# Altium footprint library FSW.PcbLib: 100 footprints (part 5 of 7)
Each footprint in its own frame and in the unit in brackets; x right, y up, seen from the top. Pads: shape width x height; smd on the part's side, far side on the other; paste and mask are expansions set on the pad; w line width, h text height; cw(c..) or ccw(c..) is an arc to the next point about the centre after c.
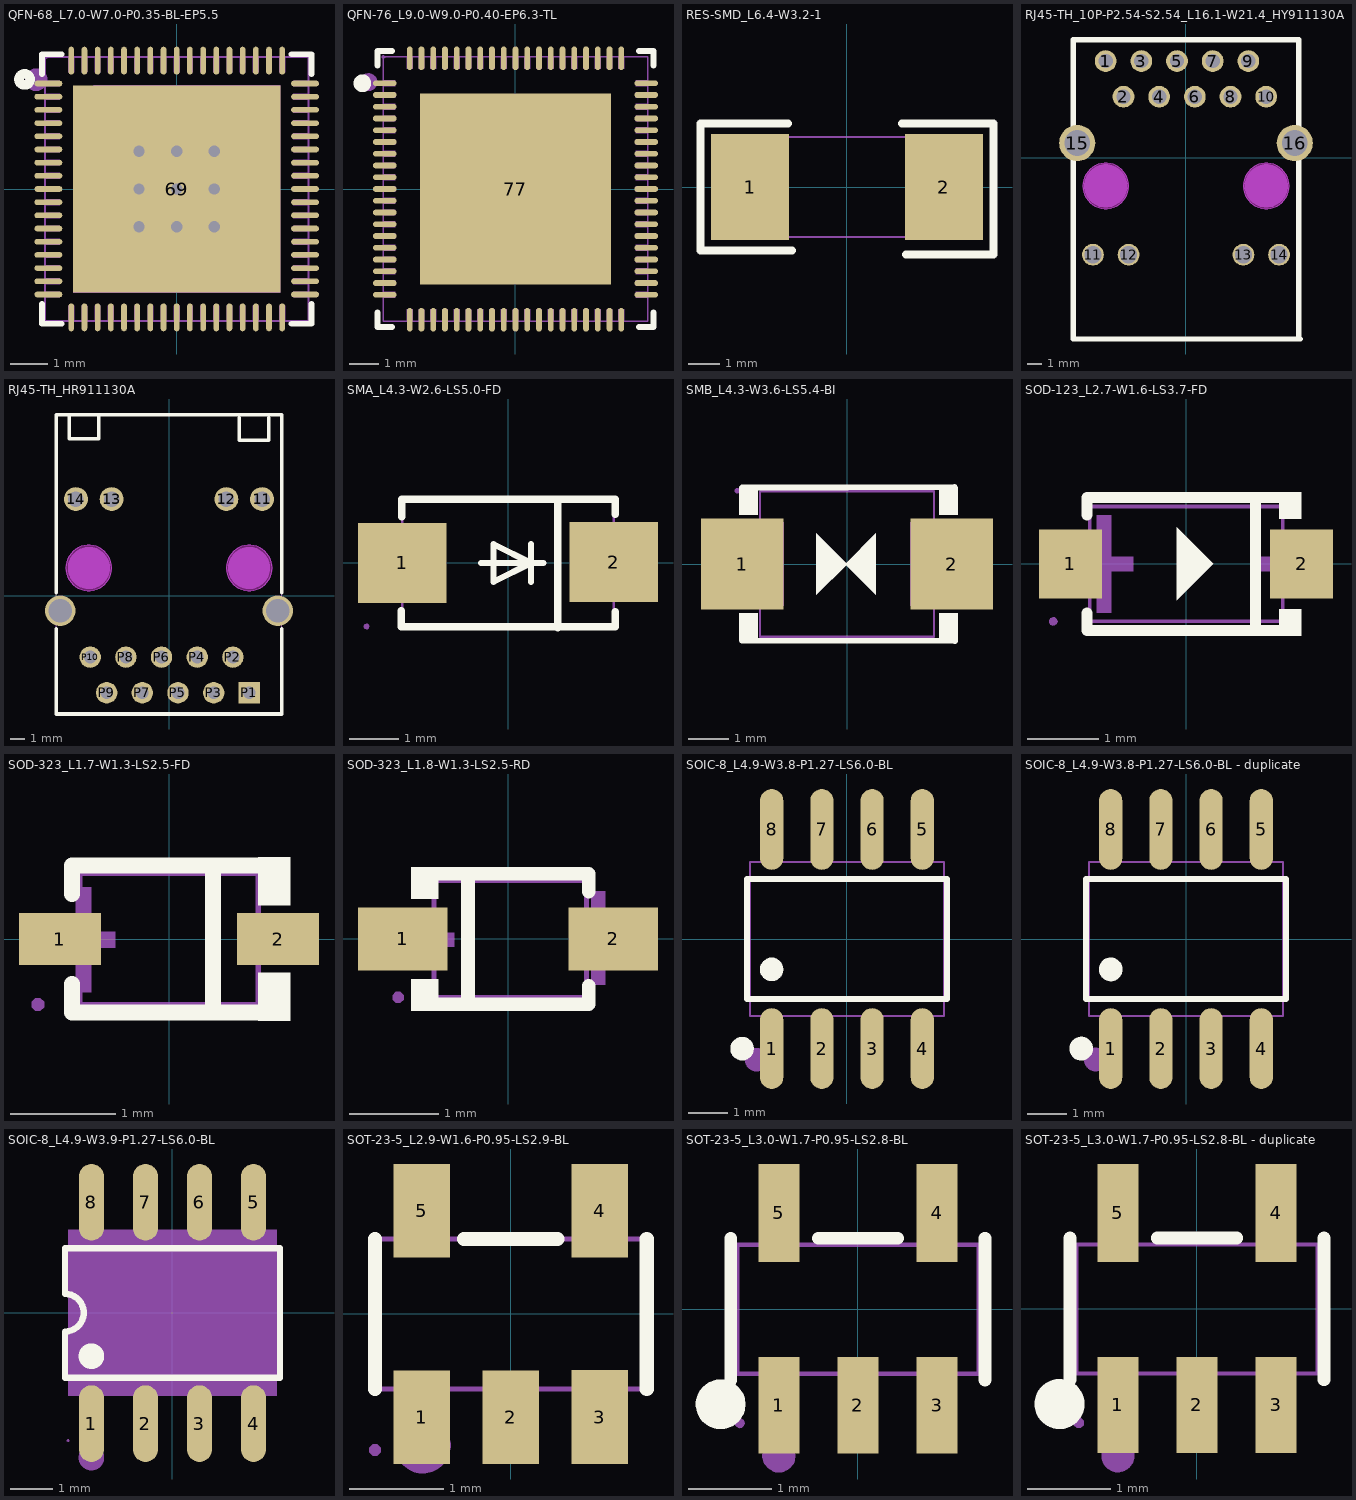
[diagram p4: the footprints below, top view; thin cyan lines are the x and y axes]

## QFN-68_L7.0-W7.0-P0.35-BL-EP5.5 [mm]
pads (69):
  oval 0.74x0.15 smd paste-100 mask+0.051: 1(-3.407,2.8) 2(-3.407,2.45) 3(-3.407,2.1) 4(-3.407,1.75) 5(-3.407,1.4) 6(-3.407,1.05) 7(-3.407,0.7) 8(-3.407,0.35) 9(-3.407,0) 10(-3.407,-0.35) 11(-3.407,-0.7) 12(-3.407,-1.05) 13(-3.407,-1.4) 14(-3.407,-1.75) 15(-3.407,-2.1) 16(-3.407,-2.45) 17(-3.407,-2.8) 35(3.407,-2.8) 36(3.407,-2.45) 37(3.407,-2.1) 38(3.407,-1.75) 39(3.407,-1.4) 40(3.407,-1.05) 41(3.407,-0.7) 42(3.407,-0.35) 43(3.407,0) 44(3.407,0.35) 45(3.407,0.7) 46(3.407,1.05) 47(3.407,1.4) 48(3.407,1.75) 49(3.407,2.1) 50(3.407,2.45) 51(3.407,2.8)
  oval 0.15x0.74 smd paste-100 mask+0.051: 18(-2.8,-3.407) 19(-2.45,-3.407) 20(-2.1,-3.407) 21(-1.75,-3.407) 22(-1.4,-3.407) 23(-1.05,-3.407) 24(-0.7,-3.407) 25(-0.35,-3.407) 26(0,-3.407) 27(0.35,-3.407) 28(0.7,-3.407) 29(1.05,-3.407) 30(1.4,-3.407) 31(1.75,-3.407) 32(2.1,-3.407) 33(2.45,-3.407) 34(2.8,-3.407) 52(2.8,3.407) 53(2.45,3.407) 54(2.1,3.407) 55(1.75,3.407) 56(1.4,3.407) 57(1.05,3.407) 58(0.7,3.407) 59(0.35,3.407) 60(0,3.407) 61(-0.35,3.407) 62(-0.7,3.407) 63(-1.05,3.407) 64(-1.4,3.407) 65(-1.75,3.407) 66(-2.1,3.407) 67(-2.45,3.407) 68(-2.8,3.407)
  rect 5.5x5.5 smd paste-100 mask+0.051: 69(0,0)
via 1,-1 diameter 0.6 hole 0.3
via 0,-1 diameter 0.6 hole 0.3
via -1,-1 diameter 0.6 hole 0.3
via 1,0 diameter 0.6 hole 0.3
via 0,0 diameter 0.6 hole 0.3
via -1,0 diameter 0.6 hole 0.3
via 1,1 diameter 0.6 hole 0.3
via 0,1 diameter 0.6 hole 0.3
via -1,1 diameter 0.6 hole 0.3
Top Overlay:
  circle w0.254: c-4.04,2.91 r0.148
  lines w0.152: -3.576,-3.05 -3.576,-3.576 -3.05,-3.576 ; -3.576,3.05 -3.576,3.576 -3.05,3.576 ; 3.05,-3.576 3.576,-3.576 3.576,-3.05 ; 3.05,3.576 3.576,3.576 3.576,3.05
Top Paste:
  drawing of 69 lines, arcs and shapes, not listed
Mechanical 2:
  circle w0.3: c-3.73,2.9 r0.15
Mechanical 6:
  lines w0.051: -3.5,-3.5 -3.5,3.5 3.5,3.5 3.5,-3.5 -3.5,-3.5
Mechanical 8:
  region: -3.44,3.5 -3.44,3.475 -3.475,3.44 -3.525,3.44 -3.56,3.475 -3.56,3.5 -3.56,3.525 -3.525,3.56 -3.475,3.56 -3.44,3.525 -3.44,3.5
Mechanical 9:
  drawing of 69 lines, arcs and shapes, not listed
3D body "QFN-68_L7.0-W7.0-P0.35-BL-EP5.5.step": height 0.75, standoff 0, extent -3.5,-3.5 3.5,3.5

## QFN-76_L9.0-W9.0-P0.40-EP6.3-TL [mm]
pads (77):
  oval 0.8x0.2 smd paste-100 mask+0.051: 1(-4.45,3.599) 2(-4.45,3.2) 3(-4.45,2.799) 4(-4.45,2.4) 5(-4.45,1.999) 6(-4.45,1.6) 7(-4.45,1.199) 8(-4.45,0.8) 9(-4.45,0.399) 10(-4.45,0) 11(-4.45,-0.399) 12(-4.45,-0.8) 13(-4.45,-1.199) 14(-4.45,-1.6) 15(-4.45,-1.999) 16(-4.45,-2.4) 17(-4.45,-2.799) 18(-4.45,-3.2) 19(-4.45,-3.599) 39(4.45,-3.599) 40(4.45,-3.2) 41(4.45,-2.799) 42(4.45,-2.4) 43(4.45,-1.999) 44(4.45,-1.6) 45(4.45,-1.199) 46(4.45,-0.8) 47(4.45,-0.399) 48(4.45,0) 49(4.45,0.399) 50(4.45,0.8) 51(4.45,1.199) 52(4.45,1.6) 53(4.45,1.999) 54(4.45,2.4) 55(4.45,2.799) 56(4.45,3.2) 57(4.45,3.599)
  oval 0.2x0.8 smd paste-100 mask+0.051: 20(-3.599,-4.45) 21(-3.2,-4.45) 22(-2.799,-4.45) 23(-2.4,-4.45) 24(-1.999,-4.45) 25(-1.6,-4.45) 26(-1.199,-4.45) 27(-0.8,-4.45) 28(-0.399,-4.45) 29(0,-4.45) 30(0.399,-4.45) 31(0.8,-4.45) 32(1.199,-4.45) 33(1.6,-4.45) 34(1.999,-4.45) 35(2.4,-4.45) 36(2.799,-4.45) 37(3.2,-4.45) 38(3.599,-4.45) 58(3.599,4.45) 59(3.2,4.45) 60(2.799,4.45) 61(2.4,4.45) 62(1.999,4.45) 63(1.6,4.45) 64(1.199,4.45) 65(0.8,4.45) 66(0.399,4.45) 67(0,4.45) 68(-0.399,4.45) 69(-0.8,4.45) 70(-1.199,4.45) 71(-1.6,4.45) 72(-1.999,4.45) 73(-2.4,4.45) 74(-2.799,4.45) 75(-3.2,4.45) 76(-3.599,4.45)
  rect 6.5x6.5 smd paste-100 mask+0.051: 77(0,0)
Top Overlay:
  lines w0.2: -4.7,-4.2 -4.7,-4.7 -4.2,-4.7 ; -4.7,4.2 -4.7,4.7 -4.2,4.7 ; 4.2,-4.7 4.7,-4.7 4.7,-4.2 ; 4.2,4.7 4.7,4.7 4.7,4.2
  lines w0.3: -5.06,3.597 cw(c-5.21,3.599) -5.06,3.6
Top Paste:
  drawing of 77 lines, arcs and shapes, not listed
Mechanical 2:
  circle w0.3: c-5,3.64 r0.15
Mechanical 6:
  lines w0.051: -4.5,-4.5 -4.5,4.5 4.5,4.5 4.5,-4.5 -4.5,-4.5
Mechanical 8:
  region: -4.44,4.5 -4.44,4.475 -4.475,4.44 -4.525,4.44 -4.56,4.475 -4.56,4.5 -4.56,4.525 -4.525,4.56 -4.475,4.56 -4.44,4.525 -4.44,4.5
Mechanical 9:
  drawing of 77 lines, arcs and shapes, not listed
3D body "QFN-76_L9.0-W9.0-P0.40-EP6.3-TL.step": height 0.85, standoff 0, extent -4.5,-4.5 4.5,4.5

## RES-SMD_L6.4-W3.2-1 [mil]
pads (2):
  rect 98.4x133.9 smd: 1(-122,0) 2(122.1,0)
Top Overlay:
  lines w10: -74.5,80 -184.5,80 -184.5,-80 -69.5,-80 ; 69.6,80 184.6,80 184.6,-85 74.6,-85
Mechanical 6:
  lines w2: -126,-63 -126,63 126,63 126,-63 -126,-63
Mechanical 8:
  region: -123.6,-63 -124,-64.3 -125,-65.1 -126.3,-65.3 -127.5,-64.8 -128.2,-63.7 -128.2,-62.3 -127.5,-61.2 -126.3,-60.7 -125,-60.8 -124,-61.7
Mechanical 9:
  region: 90.6,63 126,63 126,-63 90.6,-63
  region: -126,63 -90.5,63 -90.5,-63 -126,-63

## RJ45-TH_10P-P2.54-S2.54_L16.1-W21.4_HY911130A [mil]
pads (16):
  round 61 hole 40: 1(-225.19,271.45) 2(-175.19,171.46) 3(-125.19,271.45) 4(-75.19,171.46) 5(-25.19,271.45) 6(24.81,171.46) 7(74.81,271.45) 8(124.81,171.46) 9(174.81,271.45) 10(224.81,171.46)
  round 61 hole 48: 11(-260.82,-271.46) 12(-160.82,-271.46) 13(160.83,-271.46) 14(260.83,-271.46)
  round 101.6 hole 72: 15(-304.92,41.53) 16(304.92,41.53)
Top Overlay:
  lines w15.24: 315.75,-507.68 315.75,330.9 -315.75,330.9 -315.75,-507.68 320.02,-507.68
Keep-Out Layer:
  board cut-out: 288.98,-78.55 288.98,-84.85 286.52,-97.21 281.69,-108.85 274.69,-119.33 265.78,-128.24 255.3,-135.24 243.66,-140.06 231.3,-142.52 218.7,-142.52 206.34,-140.06 194.7,-135.24 184.22,-128.24 175.31,-119.33 168.31,-108.85 163.48,-97.21 161.02,-84.85 161.02,-78.55 161.02,-72.24 163.48,-59.88 168.31,-48.24 175.31,-37.76 184.22,-28.85 194.7,-21.85 206.34,-17.03 218.7,-14.57 231.3,-14.57 243.66,-17.03 255.3,-21.85 265.78,-28.85 274.69,-37.76 281.69,-48.24 286.52,-59.88 288.98,-72.24 288.98,-78.55
  board cut-out: -161.02,-78.55 -161.02,-84.85 -163.48,-97.21 -168.31,-108.85 -175.31,-119.33 -184.22,-128.24 -194.7,-135.24 -206.34,-140.06 -218.7,-142.52 -231.3,-142.52 -243.66,-140.06 -255.3,-135.24 -265.78,-128.24 -274.69,-119.33 -281.69,-108.85 -286.52,-97.21 -288.98,-84.85 -288.98,-78.55 -288.98,-72.24 -286.52,-59.88 -281.69,-48.24 -274.69,-37.76 -265.78,-28.85 -255.3,-21.85 -243.66,-17.03 -231.3,-14.57 -218.7,-14.57 -206.34,-17.03 -194.7,-21.85 -184.22,-28.85 -175.31,-37.76 -168.31,-48.24 -163.48,-59.88 -161.02,-72.24 -161.02,-78.55
Keep-Out Layer:
  drawing of 6 lines, arcs and shapes, not listed
Mechanical 1:
  circle w0.1: c225,-78.55 r63.98
  circle w0.1: c-225,-78.55 r63.98
Mechanical 6:
  lines w2: -315.75,-507.68 -315.75,330.9 315.75,330.9 315.75,-507.68 -315.75,-507.68
Mechanical 8:
  region: -313.39,330.9 -313.39,329.93 -314.77,328.54 -316.73,328.54 -318.11,329.93 -318.11,330.9 -318.11,331.88 -316.73,333.26 -314.77,333.26 -313.39,331.88 -313.39,330.9
Mechanical 9:
  drawing of 18 lines, arcs and shapes, not listed

## RJ45-TH_HR911130A [mm]
pads (16):
  round 1.7 hole 1.1: 11(6.625,6.895) 12(4.085,6.895) 13(-4.085,6.895) 14(-6.625,6.895)
  rect 1.524x1.524 hole 0.91: P1(5.72,-6.895)
  round 1.524 hole 0.91: P2(4.549,-4.355) P3(3.18,-6.895) P4(2.009,-4.355) P5(0.64,-6.895) P6(-0.531,-4.355) P7(-1.9,-6.895) P8(-3.071,-4.355) P9(-4.44,-6.895) P10(-5.611,-4.355)
  round 2.159 hole 1.7: SHIELD0(-7.745,-1.055) SHIELD1(7.745,-1.055)
Top Overlay:
  lines w0.254: -8.02,-2.337 -8.02,-8.405 8.02,-8.405 8.02,-2.337 ; -8.02,0.226 -8.02,12.877 ; -8.02,12.895 8.02,12.895 8.02,0.226 ; -7.1,12.795 -7.1,11.195 -5,11.195 -5,11.995 -5,12.795 ; 4.999,12.695 4.999,11.095 7.099,11.095 7.099,11.895 7.099,12.695
Keep-Out Layer:
  board cut-out: 7.34,1.995 7.34,1.835 7.278,1.521 7.155,1.225 6.977,0.959 6.751,0.733 6.485,0.555 6.189,0.432 5.875,0.37 5.555,0.37 5.241,0.432 4.945,0.555 4.679,0.733 4.453,0.959 4.275,1.225 4.152,1.521 4.09,1.835 4.09,1.995 4.09,2.155 4.152,2.469 4.275,2.765 4.453,3.031 4.679,3.257 4.945,3.435 5.241,3.558 5.555,3.62 5.875,3.62 6.189,3.558 6.485,3.435 6.751,3.257 6.977,3.031 7.155,2.765 7.278,2.469 7.34,2.155 7.34,1.995
  board cut-out: -4.09,1.995 -4.09,1.835 -4.152,1.521 -4.275,1.225 -4.453,0.959 -4.679,0.733 -4.945,0.555 -5.241,0.432 -5.555,0.37 -5.875,0.37 -6.189,0.432 -6.485,0.555 -6.751,0.733 -6.977,0.959 -7.155,1.225 -7.278,1.521 -7.34,1.835 -7.34,1.995 -7.34,2.155 -7.278,2.469 -7.155,2.765 -6.977,3.031 -6.751,3.257 -6.485,3.435 -6.189,3.558 -5.875,3.62 -5.555,3.62 -5.241,3.558 -4.945,3.435 -4.679,3.257 -4.453,3.031 -4.275,2.765 -4.152,2.469 -4.09,2.155 -4.09,1.995
Keep-Out Layer:
  drawing of 6 lines, arcs and shapes, not listed
Mechanical 1:
  circle w0.003: c5.715,1.995 r1.625
  circle w0.003: c-5.715,1.995 r1.625
Mechanical 2:
  circle w1.5: c-5.7,1.995 r0.75
  circle w1.5: c5.7,1.995 r0.75
Mechanical 6:
  lines w0.051: -8.02,-8.405 8.02,-8.405 8.02,12.895 -8.02,12.895 -8.02,-8.405
Mechanical 8:
  region: 8.08,12.895 8.08,12.87 8.045,12.835 7.995,12.835 7.96,12.87 7.96,12.895 7.96,12.92 7.995,12.955 8.045,12.955 8.08,12.92 8.08,12.895
Mechanical 9:
  region: 6.896,6.645 6.396,6.645 6.396,7.145 6.896,7.145
  region: 4.356,6.645 3.856,6.645 3.856,7.145 4.356,7.145
  region: -3.814,6.645 -4.314,6.645 -4.314,7.145 -3.814,7.145
  region: 5.92,-7.095 5.52,-7.095 5.52,-6.695 5.92,-6.695
  region: -7.595,-0.455 -7.595,-1.655 -7.895,-1.655 -7.895,-0.455
  region: 7.895,-0.455 7.895,-1.655 7.595,-1.655 7.595,-0.455
  region: -6.354,6.645 -6.854,6.645 -6.854,7.145 -6.354,7.145
  region: 4.749,-4.555 4.349,-4.555 4.349,-4.155 4.749,-4.155
  region: 3.38,-7.095 2.98,-7.095 2.98,-6.695 3.38,-6.695
  region: 2.209,-4.555 1.809,-4.555 1.809,-4.155 2.209,-4.155
  region: 0.84,-7.095 0.44,-7.095 0.44,-6.695 0.84,-6.695
  region: -0.331,-4.555 -0.731,-4.555 -0.731,-4.155 -0.331,-4.155
  region: -1.7,-7.095 -2.1,-7.095 -2.1,-6.695 -1.7,-6.695
  region: -2.871,-4.555 -3.271,-4.555 -3.271,-4.155 -2.871,-4.155
  region: -4.24,-7.095 -4.64,-7.095 -4.64,-6.695 -4.24,-6.695
  region: -5.411,-4.555 -5.811,-4.555 -5.811,-4.155 -5.411,-4.155
3D body "RJ45-TH_HR911130A.step": height 13.5, standoff -4, extent -8.128,-8.491 8.012,12.809

## SMA_L4.3-W2.6-LS5.0-FD [mm]
pads (2):
  rect 1.801x1.621 smd: 1(-2.151,-0.008) 2(2.149,0.01)
Top Overlay:
  lines w0.127: -0.551,-0.01 0.719,-0.01 ; 0.465,-0.391 0.465,-0.01 ; 0.465,0.371 0.465,-0.01 ; 0.465,-0.01 -0.297,0.371 -0.297,-0.01 -0.297,-0.391 0.465,-0.01
  lines w0.152: -2.172,-0.978 -2.172,-1.308 2.177,-1.308 2.177,-0.996 ; -2.162,0.932 -2.162,1.29 2.184,1.29 2.184,0.978 ; 1.006,-1.321 1.006,1.278
Mechanical 2:
  region: 2.431,0.097 2.431,-0.097 1.659,-0.097 1.659,0.097
  region: -2.433,0.097 -2.433,-0.097 -1.661,-0.097 -1.661,0.097
  region: -2.144,0.645 -2.144,-0.643 -1.951,-0.643 -1.951,0.645
Mechanical 6:
  lines w0.051: -2.151,-1.298 2.149,-1.298 2.149,1.3 -2.151,1.3 -2.151,-1.298
Mechanical 8:
  region: -2.819,-1.298 -2.83,-1.331 -2.855,-1.354 -2.888,-1.359 -2.918,-1.344 -2.936,-1.316 -2.936,-1.283 -2.918,-1.255 -2.888,-1.24 -2.855,-1.245 -2.83,-1.267
Mechanical 9:
  region: -2.499,-0.734 -2.499,0.716 -1.351,0.716 -1.351,-0.734
  region: 2.499,0.737 2.499,-0.714 1.349,-0.714 1.349,0.737

## SMB_L4.3-W3.6-LS5.4-BI [mm]
pads (2):
  rect 2.047x2.241 smd: 1(-2.591,0) 2(2.591,0)
Top Overlay:
  region: -2.667,-1.905 -2.667,-1.215 -2.21,-1.215 -2.21,-1.905
  region: -2.667,1.905 -2.667,1.215 -2.21,1.215 -2.21,1.905
  region: 2.286,1.905 2.286,1.215 2.743,1.215 2.743,1.905
  region: 2.286,-1.905 2.286,-1.215 2.743,-1.215 2.743,-1.905
  region: 0,0 -0.762,0.762 -0.762,-0.762
  region: -0.045,-0.004 0.717,-0.766 0.717,0.758
  lines w0.152: -2.599,-1.89 2.667,-1.905 ; -2.591,1.887 2.663,1.905
Mechanical 6:
  lines w0.051: -2.15,-1.8 -2.15,1.8 2.15,1.8 2.15,-1.8 -2.15,-1.8
Mechanical 8:
  region: -2.659,1.816 -2.659,1.791 -2.694,1.756 -2.744,1.756 -2.779,1.791 -2.779,1.816 -2.779,1.841 -2.744,1.876 -2.694,1.876 -2.659,1.841 -2.659,1.816
Mechanical 9:
  region: -2.708,1.037 -2.708,-1.037 -1.568,-1.037 -1.568,1.037
  region: 2.708,1.037 2.708,-1.037 1.568,-1.037 1.568,1.037
3D body "SMB_L4.3-W3.6-LS5.4-BI.step": height 2.96, standoff -0.01, extent -2.573,-1.81 2.827,1.81

## SOD-123_L2.7-W1.6-LS3.7-FD [mm]
pads (2):
  rect 0.879x0.96 smd: 1(-1.61,0) 2(1.61,0)
Top Overlay:
  region: 0.381,0 -0.127,0.508 -0.127,-0.508
  region: 1.3,1.001 1.3,0.632 1.605,0.632 1.605,1.001
  region: 1.3,-1.003 1.3,-0.632 1.605,-0.632 1.605,-1.003
  lines w0.152: -1.377,-0.683 -1.377,-0.927 1.377,-0.927 ; -1.377,0.683 -1.377,0.925 1.377,0.925 ; 0.968,-0.927 0.968,0.925
Mechanical 2:
  region: -1.245,-0.681 -1.245,0.678 -1.041,0.678 -1.041,-0.681
  region: -1.552,-0.102 -1.552,0.102 -0.734,0.102 -0.734,-0.102
  region: 1.806,-0.102 1.806,0.102 0.991,0.102 0.988,-0.102
Mechanical 6:
  lines w0.051: -1.344,-0.8 -1.344,0.8 1.346,0.8 1.346,-0.8 -1.344,-0.8
Mechanical 7:
  region: -1.511,0.3 -1.511,-0.3 -1.339,-0.3 -1.339,0.3
  region: 1.511,-0.3 1.511,0.3 1.341,0.3 1.341,-0.3
Mechanical 8:
  region: -1.791,-0.8 -1.801,-0.833 -1.826,-0.856 -1.859,-0.861 -1.89,-0.846 -1.908,-0.818 -1.908,-0.785 -1.89,-0.754 -1.859,-0.742 -1.826,-0.747 -1.801,-0.77
Mechanical 9:
  region: -1.852,0.3 -1.501,0.3 -1.501,-0.3 -1.852,-0.3
  region: 1.852,-0.3 1.501,-0.3 1.501,0.3 1.852,0.3

## SOD-323_L1.7-W1.3-LS2.5-FD [mm]
pads (2):
  rect 0.78x0.5 smd: 1(-1.04,0) 2(1.04,0)
Top Overlay:
  region: 0.85,0.32 1.155,0.32 1.155,0.777 0.85,0.777
  region: 0.85,-0.32 1.155,-0.32 1.155,-0.777 0.85,-0.777
  lines w0.152: -0.926,-0.43 -0.926,-0.701 0.926,-0.701 ; -0.926,0.43 -0.926,0.701 0.926,0.701 ; 0.421,-0.701 0.421,0.701
Mechanical 2:
  region: -1.114,-0.083 -1.114,0.067 -0.514,0.067 -0.514,-0.083
  region: 1.316,-0.075 1.316,0.075 0.716,0.075 0.716,-0.075
  region: -0.889,-0.508 -0.889,0.492 -0.739,0.492 -0.739,-0.508
Mechanical 6:
  lines w0.051: -0.85,-0.625 0.85,-0.625 0.85,0.625 -0.85,0.625 -0.85,-0.625
Mechanical 7:
  region: -0.96,-0.16 -0.84,-0.16 -0.84,0.16 -0.96,0.16
  region: 0.96,-0.16 0.84,-0.16 0.84,0.16 0.96,0.16
Mechanical 8:
  region: -1.19,-0.625 -1.19,-0.65 -1.225,-0.685 -1.275,-0.685 -1.31,-0.65 -1.31,-0.625 -1.31,-0.6 -1.275,-0.565 -1.225,-0.565 -1.19,-0.6 -1.19,-0.625
Mechanical 9:
  region: -1.25,-0.16 -0.95,-0.16 -0.95,0.16 -1.25,0.16
  region: 1.25,-0.16 0.95,-0.16 0.95,0.16 1.25,0.16
3D body "SOD-323_L1.7-W1.3-LS2.5-FD.step": height 0.96, standoff 0.01, extent -1.25,-0.625 1.25,0.625

## SOD-323_L1.8-W1.3-LS2.5-RD [mm]
pads (2):
  rect 1x0.7 smd: 1(-1.172,0) 2(1.172,0)
Top Overlay:
  region: -0.775,0.802 -0.775,0.45 -1.08,0.45 -1.08,0.802
  region: -0.775,-0.803 -0.775,-0.45 -1.08,-0.45 -1.08,-0.803
  lines w0.152: -0.851,-0.726 0.901,-0.726 0.901,-0.52 ; -0.851,0.726 0.901,0.726 0.901,0.53 ; -0.447,-0.726 -0.447,0.726
Mechanical 2:
  region: -1.225,0.07 -1.225,-0.086 -0.601,-0.086 -0.601,0.07
  region: 1.315,0.09 1.315,-0.066 0.691,-0.066 0.691,0.09
  region: 1.083,0.53 1.083,-0.51 0.927,-0.51 0.927,0.53
Mechanical 6:
  lines w0.051: -0.825,-0.65 -0.825,0.65 0.875,0.65 0.875,-0.65 -0.825,-0.65
Mechanical 7:
  region: 0.985,0.16 0.985,-0.16 0.865,-0.16 0.865,0.16
  region: -0.815,0.16 -0.815,-0.16 -0.935,-0.16 -0.935,0.16
Mechanical 8:
  region: -1.165,-0.65 -1.165,-0.675 -1.2,-0.71 -1.25,-0.71 -1.285,-0.675 -1.285,-0.65 -1.285,-0.625 -1.25,-0.59 -1.2,-0.59 -1.165,-0.625 -1.165,-0.65
Mechanical 9:
  region: 1.275,0.16 1.275,-0.16 0.975,-0.16 0.975,0.16
  region: -0.925,0.16 -0.925,-0.16 -1.225,-0.16 -1.225,0.16
3D body "SOD-323_L1.8-W1.3-LS2.5-RD.step": height 0.95, standoff 0, extent -1.325,-0.65 1.325,0.65

## SOIC-8_L4.9-W3.8-P1.27-LS6.0-BL [mil]
pads (8):
  oval 23.1x80.5 smd: 1(-75,-109.1) 2(-25,-109.1) 3(25,-109.1) 4(75,-109.1) 5(75,109.2) 6(25,109.2) 7(-25,109.2) 8(-75,109.2)
Top Overlay:
  lines w6: -99.5,-59.9 99.5,-59.9 99.5,59.9 -99.5,59.9 -99.5,-59.9
  lines w11.8: -110.3,-109.1 -109.9,-107.1 -108.9,-105.3 -107.3,-104 -105.4,-103.3 -103.4,-103.3 -101.4,-104 -99.9,-105.3 -98.8,-107.1 -98.5,-109.1 -98.8,-111.2 -99.9,-112.9 -101.4,-114.3 -103.4,-115 -105.4,-115 -107.3,-114.3 -108.9,-112.9 -109.9,-111.2 -110.3,-109.1 ; -80.9,-30.3 -80.6,-28.3 -79.5,-26.5 -78,-25.2 -76,-24.5 -74,-24.5 -72,-25.2 -70.5,-26.5 -69.4,-28.3 -69.1,-30.3 -69.4,-32.3 -70.5,-34.1 -72,-35.4 -74,-36.1 -76,-36.1 -78,-35.4 -79.5,-34.1 -80.6,-32.3 -80.9,-30.3
Mechanical 2:
  lines w11.8: -95.9,-120 -95.6,-118 -94.5,-116.2 -93,-114.9 -91,-114.2 -89,-114.2 -87,-114.9 -85.5,-116.2 -84.5,-118 -84.1,-120 -84.5,-122 -85.5,-123.8 -87,-125.1 -89,-125.8 -91,-125.8 -93,-125.1 -94.5,-123.8 -95.6,-122 -95.9,-120
Mechanical 6:
  lines w2: -96.5,-76.8 96.5,-76.8 96.5,76.8 -96.5,76.8 -96.5,-76.8
Mechanical 7:
  region: -83.3,-85.6 -83.3,-76.4 -66.7,-76.4 -66.7,-85.6
  region: -33.3,-85.6 -33.3,-76.4 -16.7,-76.4 -16.7,-85.6
  region: 16.7,-85.6 16.7,-76.4 33.3,-76.4 33.3,-85.6
  region: 66.7,-85.6 66.7,-76.4 83.3,-76.4 83.3,-85.6
  region: -83.3,85.6 -83.3,76.4 -66.7,76.4 -66.7,85.6
  region: -33.3,85.6 -33.3,76.4 -16.7,76.4 -16.7,85.6
  region: 16.7,85.6 16.7,76.4 33.3,76.4 33.3,85.6
  region: 66.7,85.6 66.7,76.4 83.3,76.4 83.3,85.6
Mechanical 8:
  region: -94.1,-118.1 -94.5,-119.4 -95.5,-120.3 -96.8,-120.4 -98,-119.9 -98.7,-118.8 -98.7,-117.4 -98,-116.3 -96.8,-115.8 -95.5,-116 -94.5,-116.8
Mechanical 9:
  region: -83.3,-118.1 -83.3,-85.2 -66.7,-85.2 -66.7,-118.1
  region: -33.3,-118.1 -33.3,-85.2 -16.7,-85.2 -16.7,-118.1
  region: 16.7,-118.1 16.7,-85.2 33.3,-85.2 33.3,-118.1
  region: 66.7,-118.1 66.7,-85.2 83.3,-85.2 83.3,-118.1
  region: -83.3,118.1 -83.3,85.2 -66.7,85.2 -66.7,118.1
  region: -33.3,118.1 -33.3,85.2 -16.7,85.2 -16.7,118.1
  region: 16.7,118.1 16.7,85.2 33.3,85.2 33.3,118.1
  region: 66.7,118.1 66.7,85.2 83.3,85.2 83.3,118.1

## SOIC-8_L4.9-W3.8-P1.27-LS6.0-BL - duplicate [mm]
pads (8):
  oval 0.588x2.045 smd: 1(-1.905,-2.772) 2(-0.635,-2.772) 3(0.635,-2.772) 4(1.905,-2.772) 5(1.905,2.772) 6(0.635,2.772) 7(-0.635,2.772) 8(-1.905,2.772)
Top Overlay:
  circle w0.3: c-1.905,-0.769 r0.15
  circle w0.3: c-2.652,-2.772 r0.15
  lines w0.152: -2.526,-1.521 2.526,-1.521 2.526,1.521 -2.526,1.521 -2.526,-1.521
Mechanical 2:
  circle w0.3: c-2.286,-3.048 r0.15
Mechanical 6:
  lines w0.051: -2.45,-1.95 2.45,-1.95 2.45,1.95 -2.45,1.95 -2.45,-1.95
Mechanical 7:
  region: -2.115,-2.175 -2.115,-1.94 -1.695,-1.94 -1.695,-2.175
  region: -0.845,-2.175 -0.845,-1.94 -0.425,-1.94 -0.425,-2.175
  region: 0.425,-2.175 0.425,-1.94 0.845,-1.94 0.845,-2.175
  region: 1.695,-2.175 1.695,-1.94 2.115,-1.94 2.115,-2.175
  region: -2.115,2.175 -2.115,1.94 -1.695,1.94 -1.695,2.175
  region: -0.845,2.175 -0.845,1.94 -0.425,1.94 -0.425,2.175
  region: 0.425,2.175 0.425,1.94 0.845,1.94 0.845,2.175
  region: 1.695,2.175 1.695,1.94 2.115,1.94 2.115,2.175
Mechanical 8:
  region: -2.39,-3 -2.39,-3.025 -2.425,-3.06 -2.475,-3.06 -2.51,-3.025 -2.51,-3 -2.51,-2.975 -2.475,-2.94 -2.425,-2.94 -2.39,-2.975 -2.39,-3
Mechanical 9:
  region: -2.115,-3 -2.115,-2.165 -1.695,-2.165 -1.695,-3
  region: -0.845,-3 -0.845,-2.165 -0.425,-2.165 -0.425,-3
  region: 0.425,-3 0.425,-2.165 0.845,-2.165 0.845,-3
  region: 1.695,-3 1.695,-2.165 2.115,-2.165 2.115,-3
  region: -2.115,3 -2.115,2.165 -1.695,2.165 -1.695,3
  region: -0.845,3 -0.845,2.165 -0.425,2.165 -0.425,3
  region: 0.425,3 0.425,2.165 0.845,2.165 0.845,3
  region: 1.695,3 1.695,2.165 2.115,2.165 2.115,3

## SOIC-8_L4.9-W3.9-P1.27-LS6.0-BL [mm]
pads (8):
  oval 0.588x1.8 smd paste+0 mask+0.051: 1(-1.905,-2.6) 2(-0.635,-2.6) 3(0.635,-2.6) 4(1.905,-2.6) 5(1.905,2.6) 6(0.635,2.6) 7(-0.635,2.6) 8(-1.905,2.6)
Top Overlay:
  circle w0.3: c-1.905,-1.016 r0.15
  lines w0.15: -2.068,-1.521 -2.526,-1.521 ; -2.068,1.521 -2.526,1.521 ; -1.742,-1.521 -0.798,-1.521 ; -1.742,1.521 -0.798,1.521 ; -0.472,-1.521 0.472,-1.521 ; -0.472,1.521 0.472,1.521 ; 0.798,-1.521 1.742,-1.521 ; 0.798,1.521 1.742,1.521 ; 2.068,-1.521 2.526,-1.521 ; 2.068,1.521 2.526,1.521 ; -2.526,-1.521 2.526,-1.521 ; -2.526,-1.521 -2.526,-0.435 ccw(c-2.526,0.007) -2.526,0.449 -2.526,1.521 ; -2.526,1.521 2.526,1.521 ; 2.526,-1.521 2.526,1.521
Mechanical 5:
  circle w0.3: c-1.905,-3.4 r0.15
Mechanical 9:
  region: -2.45,-1.95 -2.45,1.95 2.45,1.95 2.45,-1.95
Mechanical 10:
  region: -2.115,-2.175 -2.115,-1.94 -1.695,-1.94 -1.695,-2.175
  region: -0.845,-2.175 -0.845,-1.94 -0.425,-1.94 -0.425,-2.175
  region: 0.425,-2.175 0.425,-1.94 0.845,-1.94 0.845,-2.175
  region: 1.695,-2.175 1.695,-1.94 2.115,-1.94 2.115,-2.175
  region: -2.115,2.175 -2.115,1.94 -1.695,1.94 -1.695,2.175
  region: -0.845,2.175 -0.845,1.94 -0.425,1.94 -0.425,2.175
  region: 0.425,2.175 0.425,1.94 0.845,1.94 0.845,2.175
  region: 1.695,2.175 1.695,1.94 2.115,1.94 2.115,2.175
Mechanical 11:
  region: -2.42,-3 -2.42,-3.012 -2.438,-3.03 -2.462,-3.03 -2.48,-3.012 -2.48,-3 -2.48,-2.988 -2.462,-2.97 -2.438,-2.97 -2.42,-2.988 -2.42,-3
Mechanical 12:
  region: -2.115,-3 -2.115,-2.165 -1.695,-2.165 -1.695,-3
  region: -0.845,-3 -0.845,-2.165 -0.425,-2.165 -0.425,-3
  region: 0.425,-3 0.425,-2.165 0.845,-2.165 0.845,-3
  region: 1.695,-3 1.695,-2.165 2.115,-2.165 2.115,-3
  region: -2.115,3 -2.115,2.165 -1.695,2.165 -1.695,3
  region: -0.845,3 -0.845,2.165 -0.425,2.165 -0.425,3
  region: 0.425,3 0.425,2.165 0.845,2.165 0.845,3
  region: 1.695,3 1.695,2.165 2.115,2.165 2.115,3

## SOT-23-5_L2.9-W1.6-P0.95-LS2.9-BL [mm]
pads (5):
  rect 0.6x1 smd paste+0 mask+0.05: 1(-0.95,-1.1) 2(0,-1.1) 3(0.95,-1.1) 4(0.95,1.1) 5(-0.95,1.1)
Top Overlay:
  lines w0.15: -1.45,-0.8 -1.45,0.8 ; -0.5,0.8 0.5,0.8 ; 1.45,-0.8 1.45,0.8
Mechanical 2:
  circle w0.3: c-0.94,-1.4 r0.15
Mechanical 6:
  lines w0.051: -1.45,-0.8 1.45,-0.8 1.45,0.8 -1.45,0.8 -1.45,-0.8
Mechanical 7:
  region: 0.75,-1.01 0.75,-0.79 1.15,-0.79 1.15,-1.01
  region: -0.2,-1.01 -0.2,-0.79 0.2,-0.79 0.2,-1.01
  region: -1.15,-1.01 -1.15,-0.79 -0.75,-0.79 -0.75,-1.01
  region: -0.75,1.01 -0.75,0.79 -1.15,0.79 -1.15,1.01
  region: 1.15,1.01 1.15,0.79 0.75,0.79 0.75,1.01
Mechanical 8:
  region: -1.39,-1.45 -1.39,-1.475 -1.425,-1.51 -1.475,-1.51 -1.51,-1.475 -1.51,-1.45 -1.51,-1.425 -1.475,-1.39 -1.425,-1.39 -1.39,-1.425 -1.39,-1.45
Mechanical 9:
  region: -0.2,-1.45 -0.2,-1 0.2,-1 0.2,-1.45
  region: 0.75,-1.45 0.75,-1 1.15,-1 1.15,-1.45
  region: -1.15,-1.45 -1.15,-1 -0.75,-1 -0.75,-1.45
  region: 0.75,1 0.75,1.45 1.15,1.45 1.15,1
  region: -1.15,1 -1.15,1.45 -0.75,1.45 -0.75,1

## SOT-23-5_L3.0-W1.7-P0.95-LS2.8-BL [mil]
pads (5):
  rect 19.3x45.6 smd: 1(-37.4,-45.4) 2(0,-45.4) 3(37.4,-45.4)
  rect 19.3x46.3 smd: 4(37.4,45.5) 5(-37.4,45.5)
Top Overlay:
  lines w6: -60.1,-33.5 -60.1,33.5 ; -18.7,33.5 18.8,33.5 ; 60.1,-33.5 60.1,33.5
  lines w11.8: -70.9,-45 -70.5,-42.9 -69.5,-41.2 -67.9,-39.9 -66,-39.1 -64,-39.1 -62,-39.9 -60.5,-41.2 -59.4,-42.9 -59.1,-45 -59.4,-47 -60.5,-48.8 -62,-50.1 -64,-50.8 -66,-50.8 -67.9,-50.1 -69.5,-48.8 -70.5,-47 -70.9,-45
Mechanical 2:
  lines w7.9: -41.3,-69.4 -40.9,-67.7 -39.8,-66.3 -38.3,-65.5 -36.5,-65.5 -34.9,-66.3 -33.8,-67.7 -33.5,-69.4 -33.8,-71.1 -34.9,-72.4 -36.5,-73.2 -38.3,-73.2 -39.8,-72.4 -40.9,-71.1 -41.3,-69.4
Mechanical 6:
  lines w2: -57.1,-30.5 -57.1,30.5 57.1,30.5 57.1,-30.5 -57.1,-30.5
Mechanical 7:
  region: -44.3,-39.7 -44.3,-29.1 -30.5,-29.1 -30.5,-39.7
  region: -6.9,-39.7 -6.9,-29.1 6.9,-29.1 6.9,-39.7
  region: 30.5,-39.7 30.5,-29.1 44.3,-29.1 44.3,-39.7
  region: 30.5,29.2 30.5,39.8 44.3,39.8 44.3,29.2
  region: -44.3,29.2 -44.3,39.8 -30.5,39.8 -30.5,29.2
Mechanical 8:
  region: -53.5,-53.9 -53.9,-55.2 -54.9,-56.1 -56.2,-56.2 -57.4,-55.7 -58.2,-54.6 -58.2,-53.2 -57.4,-52.1 -56.2,-51.6 -54.9,-51.8 -53.9,-52.6
Mechanical 9:
  region: -44.3,-55.1 -44.3,-39.3 -30.5,-39.3 -30.5,-55.1
  region: -6.9,-55.1 -6.9,-39.3 6.9,-39.3 6.9,-55.1
  region: 30.5,-55.1 30.5,-39.3 44.3,-39.3 44.3,-55.1
  region: 30.5,39.4 30.5,55.1 44.3,55.1 44.3,39.4
  region: -44.3,39.4 -44.3,55.1 -30.5,55.1 -30.5,39.4
3D body "SOT-23-5_L3.0-W1.7-P0.95-LS2.8-BL.step": height 47.28, standoff -1.93, extent -57.09,-59.3 57.09,59.3

## SOT-23-5_L3.0-W1.7-P0.95-LS2.8-BL - duplicate [mm]
pads (5):
  rect 0.49x1.157 smd: 1(-0.95,-1.154) 2(0,-1.154) 3(0.95,-1.154)
  rect 0.49x1.175 smd: 4(0.95,1.154) 5(-0.95,1.154)
Top Overlay:
  circle w0.3: c-1.651,-1.143 r0.15
  lines w0.152: -1.526,-0.851 -1.526,0.851 ; -0.476,0.851 0.476,0.851 ; 1.526,-0.851 1.526,0.851
Mechanical 2:
  circle w0.2: c-0.95,-1.763 r0.1
Mechanical 6:
  lines w0.051: -1.45,-0.775 1.45,-0.775 1.45,0.775 -1.45,0.775 -1.45,-0.775
Mechanical 7:
  region: -1.125,0.74 -1.125,1.01 -0.775,1.01 -0.775,0.74
  region: 0.775,0.74 0.775,1.01 1.125,1.01 1.125,0.74
  region: 0.775,-1.01 0.775,-0.74 1.125,-0.74 1.125,-1.01
  region: -0.175,-1.01 -0.175,-0.74 0.175,-0.74 0.175,-1.01
  region: -1.125,-1.01 -1.125,-0.74 -0.775,-0.74 -0.775,-1.01
Mechanical 8:
  region: -1.36,-1.37 -1.36,-1.395 -1.395,-1.43 -1.445,-1.43 -1.48,-1.395 -1.48,-1.37 -1.48,-1.345 -1.445,-1.31 -1.395,-1.31 -1.36,-1.345 -1.36,-1.37
Mechanical 9:
  region: -1.125,1 -1.125,1.4 -0.775,1.4 -0.775,1
  region: 0.775,1 0.775,1.4 1.125,1.4 1.125,1
  region: 0.775,-1.4 0.775,-1 1.125,-1 1.125,-1.4
  region: -0.175,-1.4 -0.175,-1 0.175,-1 0.175,-1.4
  region: -1.125,-1.4 -1.125,-1 -0.775,-1 -0.775,-1.4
